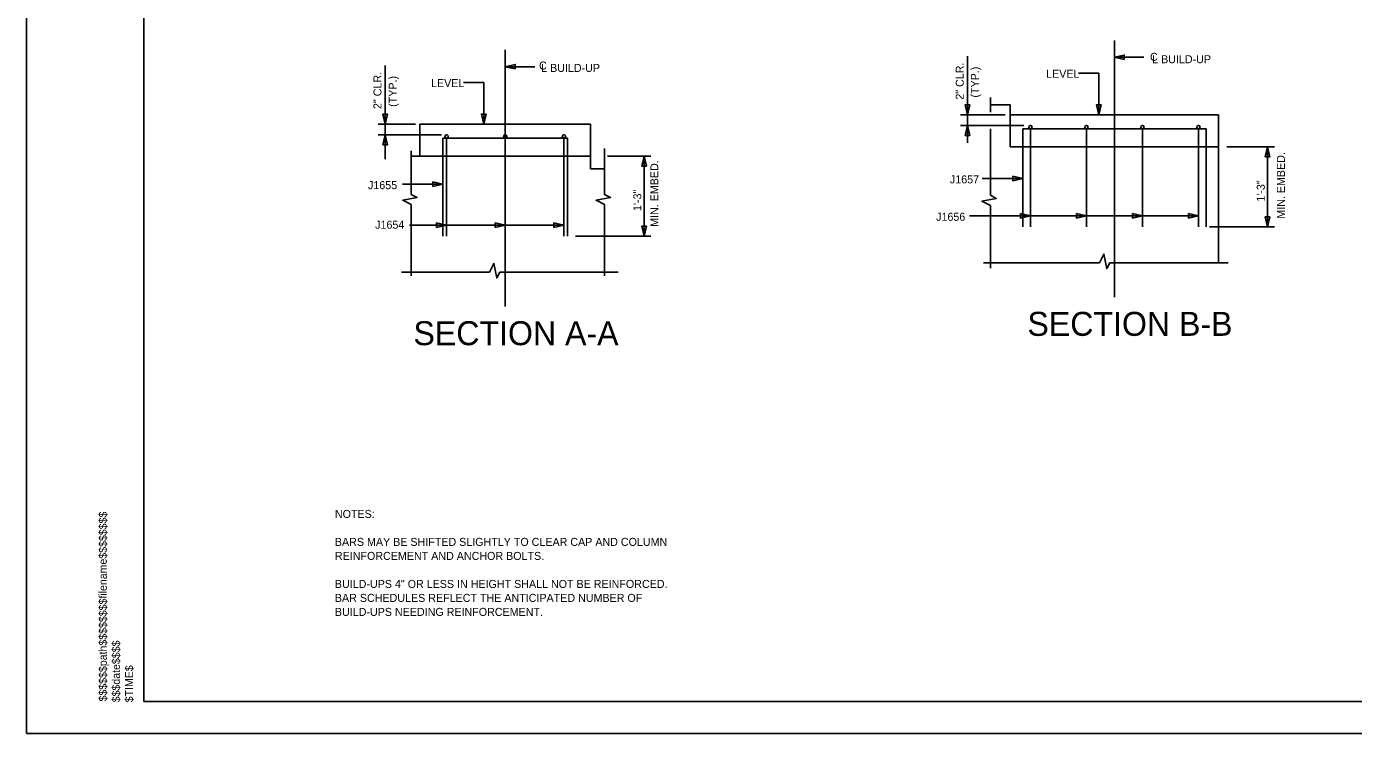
# Model space of a CAD drawing. Extents: x -133.1 to -97, y -1.7 to 20.3.
# Drawn here: x -133.14 to -112.41, y -1.69 to 9.36 of the extents above; entities that cross this region are included whole.
import ezdxf

# ---------------------------------------------------------------- set-up
doc = ezdxf.new("R2010")
doc.units = 0
for name, color, linetype in [('BR_AUTO DIMENSION', 7, 'Continuous'), ('BR_BORDER LINES', 7, 'Continuous'), ('BR_CENTER LINES', 7, 'Continuous'), ('BR_CONCRETE', 7, 'Continuous'), ('BR_REBAR', 7, 'Continuous'), ('BR_TEXT', 7, 'Continuous'), ('Default', 7, 'Continuous'), ('Level 31', 7, 'Continuous'), ('RD_SHT_ID', 7, 'Continuous')]:
    doc.layers.add(name, color=color, linetype=linetype)

msp = doc.modelspace()

# ---------------------------------------------------------------- linework, layer by layer
at = {"layer": 'BR_AUTO DIMENSION'}
for p, q in [((-127.537, 8.748), (-127.537, 7.283)), ((-125.662, 8.728), (-125.203, 8.728)), ((-118.442, 8.894), (-118.442, 7.539)), ((-116.148, 8.874), (-115.688, 8.874)), ((-116.706, 8.627), (-116.389, 8.627)), ((-116.389, 8.627), (-116.389, 7.977)), ((-126.315, 8.482), (-125.998, 8.482)), ((-125.998, 8.482), (-125.998, 7.831)), ((-117.856, 7.977), (-118.551, 7.977)), ((-127.065, 7.831), (-127.646, 7.831)), ((-117.563, 7.811), (-118.551, 7.811)), ((-126.659, 7.665), (-127.646, 7.665)), ((-114.391, 7.476), (-113.648, 7.476)), ((-113.754, 7.476), (-113.754, 6.226)), ((-124.067, 7.33), (-123.387, 7.33)), ((-123.493, 7.33), (-123.493, 6.08)), ((-126.636, 6.892), (-127.268, 6.892)), ((-117.58, 6.982), (-118.212, 6.982)), ((-124.746, 6.252), (-127.158, 6.252)), ((-126.579, 6.252), (-126.659, 6.252)), ((-125.662, 6.252), (-125.743, 6.252)), ((-124.746, 6.252), (-124.826, 6.252)), ((-114.835, 6.398), (-118.411, 6.398)), ((-118.231, 6.398), (-118.311, 6.398)), ((-117.46, 6.398), (-117.541, 6.398)), ((-116.585, 6.398), (-116.666, 6.398)), ((-115.71, 6.398), (-115.791, 6.398)), ((-114.835, 6.398), (-114.916, 6.398)), ((-114.659, 6.226), (-113.648, 6.226)), ((-124.568, 6.08), (-123.387, 6.08))]:
    msp.add_line(p, q, dxfattribs=at)
for points in [[(-125.506, 8.692), (-125.662, 8.728), (-125.506, 8.764)], [(-115.992, 8.838), (-116.148, 8.874), (-115.992, 8.91)], [(-118.406, 8.133), (-118.442, 7.977), (-118.478, 8.133)], [(-116.353, 8.133), (-116.389, 7.977), (-116.425, 8.133)], [(-127.501, 7.987), (-127.537, 7.831), (-127.573, 7.987)], [(-125.962, 7.987), (-125.998, 7.831), (-126.034, 7.987)], [(-118.478, 7.655), (-118.442, 7.811), (-118.406, 7.655)], [(-127.573, 7.509), (-127.537, 7.665), (-127.501, 7.509)], [(-113.79, 7.32), (-113.754, 7.476), (-113.718, 7.32)], [(-123.529, 7.174), (-123.493, 7.33), (-123.457, 7.174)], [(-126.792, 6.928), (-126.636, 6.892), (-126.792, 6.856)], [(-117.736, 7.018), (-117.58, 6.982), (-117.736, 6.946)], [(-117.616, 6.434), (-117.46, 6.398), (-117.616, 6.362)], [(-116.741, 6.434), (-116.585, 6.398), (-116.741, 6.362)], [(-115.866, 6.434), (-115.71, 6.398), (-115.866, 6.362)], [(-114.991, 6.434), (-114.835, 6.398), (-114.991, 6.362)], [(-126.735, 6.288), (-126.579, 6.252), (-126.735, 6.216)], [(-125.818, 6.288), (-125.662, 6.252), (-125.818, 6.216)], [(-124.902, 6.288), (-124.746, 6.252), (-124.902, 6.216)], [(-123.457, 6.236), (-123.493, 6.08), (-123.529, 6.236)], [(-113.718, 6.382), (-113.754, 6.226), (-113.79, 6.382)]]:
    msp.add_lwpolyline(points, close=True, dxfattribs=at)
at = {"layer": 'BR_BORDER LINES'}
for q in [(-131.308, 19.809), (-97.642, -1.191)]:
    msp.add_line((-131.308, -1.191), q, dxfattribs=at)
at = {"layer": 'BR_CENTER LINES'}
for p, q in [((-116.148, 9.135), (-116.148, 5.127)), ((-125.662, 8.989), (-125.662, 4.981))]:
    msp.add_line(p, q, dxfattribs=at)
at = {"layer": 'BR_CONCRETE'}
for p, q in [((-117.773, 8.132), (-118.083, 8.132)), ((-117.773, 8.132), (-117.773, 7.476)), ((-117.773, 7.977), (-114.523, 7.977)), ((-114.523, 7.977), (-114.523, 7.476)), ((-126.996, 7.831), (-126.996, 7.33)), ((-126.996, 7.831), (-124.329, 7.831)), ((-124.329, 7.831), (-124.329, 7.13)), ((-117.773, 7.476), (-114.523, 7.476)), ((-114.523, 7.476), (-114.523, 5.664)), ((-127.13, 7.33), (-124.329, 7.33)), ((-124.329, 7.13), (-124.11, 7.13))]:
    msp.add_line(p, q, dxfattribs=at)
at = {"layer": 'BR_REBAR'}
for p, q in [((-117.58, 7.759), (-117.58, 6.226)), ((-114.716, 7.759), (-117.58, 7.759)), ((-117.46, 6.226), (-117.46, 7.759)), ((-116.585, 6.226), (-116.585, 7.759)), ((-115.71, 6.226), (-115.71, 7.759)), ((-114.835, 6.226), (-114.835, 7.759)), ((-114.716, 7.759), (-114.716, 6.226)), ((-126.636, 7.613), (-126.636, 6.08)), ((-124.688, 7.613), (-126.636, 7.613)), ((-126.579, 6.08), (-126.579, 7.613)), ((-125.662, 6.08), (-125.662, 7.613)), ((-124.746, 6.08), (-124.746, 7.613)), ((-124.688, 7.613), (-124.688, 6.08))]:
    msp.add_line(p, q, dxfattribs=at)
for centre in [(-117.46, 7.785), (-116.585, 7.785), (-115.71, 7.785), (-114.835, 7.785), (-126.579, 7.639), (-125.662, 7.639), (-124.746, 7.639)]:
    msp.add_circle(centre, 0.0261, dxfattribs=at)
at = {"layer": 'Default'}
for p, q in [((-118.083, 8.016), (-118.083, 8.245)), ((-118.083, 6.718), (-118.083, 7.758)), ((-127.13, 6.733), (-127.13, 7.414)), ((-124.11, 6.733), (-124.11, 7.451)), ((-127.13, 5.46), (-127.13, 6.572)), ((-124.11, 5.46), (-124.11, 6.572)), ((-118.083, 5.577), (-118.083, 6.557)), ((-118.19, 5.664), (-116.379, 5.664)), ((-116.218, 5.664), (-114.369, 5.664)), ((-127.285, 5.518), (-125.908, 5.518)), ((-125.746, 5.518), (-123.897, 5.518))]:
    msp.add_line(p, q, dxfattribs=at)
for points in [[(-127.13, 6.733), (-127.039, 6.684), (-127.265, 6.641), (-127.13, 6.572)], [(-124.11, 6.733), (-124.018, 6.684), (-124.245, 6.641), (-124.11, 6.572)], [(-118.083, 6.718), (-117.992, 6.669), (-118.218, 6.626), (-118.083, 6.557)], [(-125.746, 5.518), (-125.796, 5.427), (-125.839, 5.653), (-125.908, 5.518)], [(-116.218, 5.664), (-116.267, 5.573), (-116.31, 5.799), (-116.379, 5.664)]]:
    msp.add_lwpolyline(points, dxfattribs=at)
at = {"layer": 'Level 31'}
msp.add_lwpolyline([(-133.141, -1.691), (-97.141, -1.691), (-97.141, 20.309), (-133.141, 20.309)], close=True, dxfattribs=at)

# ---------------------------------------------------------------- texts
at = {"layer": 'BR_AUTO DIMENSION'}
for s, p in [('C', (-115.591, 8.819)), ('C', (-125.136, 8.683)), ('L BUILD-UP', (-125.102, 8.646)), ('L BUILD-UP', (-115.557, 8.782)), ('NOTES:', (-128.324, 1.677)), ('BARS MAY BE SHIFTED SLIGHTLY TO CLEAR CAP AND COLUMN', (-128.324, 1.24)), ('REINFORCEMENT AND ANCHOR BOLTS.', (-128.324, 1.021)), ('BUILD-UPS 4" OR LESS IN HEIGHT SHALL NOT BE REINFORCED.', (-128.324, 0.583)), ('BAR SCHEDULES REFLECT THE ANTICIPATED NUMBER OF', (-128.324, 0.365)), ('BUILD-UPS NEEDING REINFORCEMENT.', (-128.324, 0.146))]:
    msp.add_text(s, height=0.125, dxfattribs=at).set_placement(p)
for s, rotation, p in [('2" CLR.', 90, (-118.501, 8.212)), ('(TYP.)', 90, (-118.264, 8.245)), ('2" CLR.', 90, (-127.597, 8.066)), ('(TYP.)', 90, (-127.359, 8.1)), ('LEVEL', 360, (-126.822, 8.409)), ('LEVEL', 360, (-117.213, 8.554)), ('MIN. EMBED.', 90, (-113.484, 6.353)), ('MIN. EMBED.', 90, (-123.271, 6.225)), ('J1655', 360, (-127.807, 6.814)), ('J1657', 360, (-118.717, 6.904)), ('1\'-3" ', 90, (-113.798, 6.619)), ('1\'-3" ', 90, (-123.537, 6.473)), ('J1656', 360, (-118.932, 6.32)), ('J1654', 360, (-127.695, 6.196))]:
    msp.add_text(s, height=0.125, rotation=rotation, dxfattribs=at).set_placement(p)
at = {"layer": 'BR_TEXT'}
for s, p in [('SECTION B-B', (-117.506, 4.522)), ('SECTION A-A', (-127.097, 4.376))]:
    msp.add_text(s, height=0.375, rotation=360, dxfattribs=at).set_placement(p)
at = {"layer": 'RD_SHT_ID'}
for s, height, p in [('$$$$$$path$$$$$$$$filename$$$$$$$$', 0.12347, (-131.887, -1.191)), ('$$$date$$$$', 0.12347, (-131.682, -1.204)), ('$TIME$', 0.1235, (-131.477, -1.204))]:
    msp.add_text(s, height=height, rotation=90, dxfattribs=at).set_placement(p)

doc.saveas('drawing.dxf')
